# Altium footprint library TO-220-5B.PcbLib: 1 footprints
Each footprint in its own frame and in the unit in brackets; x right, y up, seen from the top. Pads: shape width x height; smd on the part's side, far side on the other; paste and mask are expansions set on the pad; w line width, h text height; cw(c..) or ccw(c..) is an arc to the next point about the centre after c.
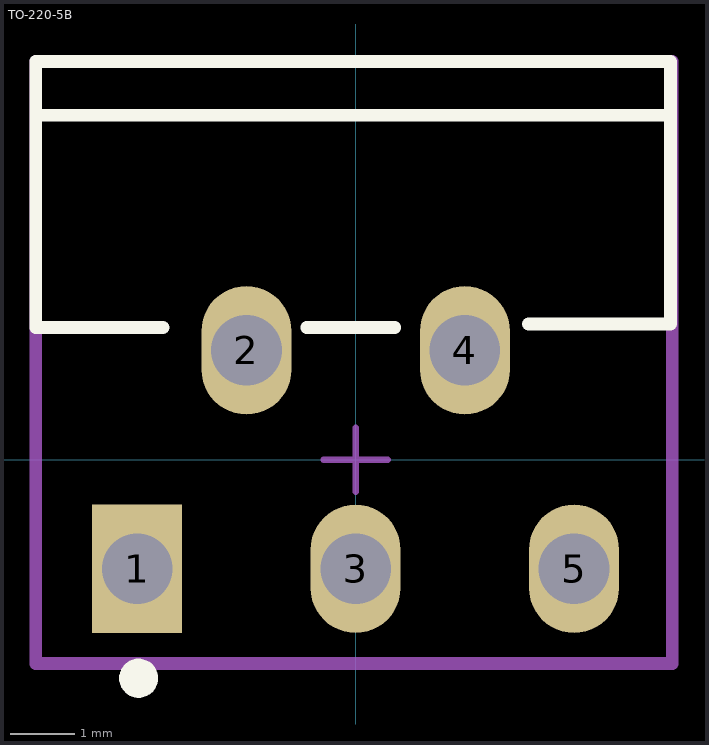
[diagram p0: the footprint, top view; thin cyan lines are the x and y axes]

## TO-220-5B [mm] "TO, Thru-Hole, Vertical, Heatsink Mounted; 5 In-Line Leads; Pitch 1.70 mm"
height 19.6
pads (5):
  rect 1.4x2 hole 1.1: 1(-3.4,-1.7)
  oval 1.4x2 hole 1.1: 2(-1.7,1.7) 3(0,-1.7) 4(1.7,1.7) 5(3.4,-1.7)
Top Overlay:
  circle w0.35: c-3.378,-3.404 r0.13
  lines w0.2: -4.928,5.359 4.902,5.359 ; -2.997,2.057 -4.978,2.057 -4.978,6.198 -4.953,6.198 4.902,6.198 4.902,2.286 4.902,2.108 2.692,2.108 ; -0.762,2.057 0.61,2.057
Mechanical 15:
  lines w0.1: -0.5,-0.002 0.5,-0.002 ; 0,-0.502 0,0.498
  lines w0.2: -4.978,-3.175 4.928,-3.175 4.928,6.198 -4.978,6.198 -4.978,-3.175
3D body "TO-220-5.STEP": height 19.75, standoff -2.91, extent -5.076,-2.313 5.084,6.186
